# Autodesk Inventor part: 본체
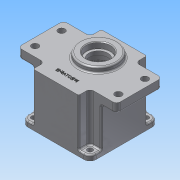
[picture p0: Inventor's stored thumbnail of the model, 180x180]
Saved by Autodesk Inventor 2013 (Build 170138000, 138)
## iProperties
Created: 2014-12
Part Number: 본체
Material: Aluminum 6061
Document SubType Name: Modeling
Designer: Administrator
Density: 2.71 g/cm^3
Mass: 705.358 g
Surface Area: 672.962 cm^2
Volume: 260.28 cm^3
Author: Administrator
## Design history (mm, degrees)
sketch "Sketch1"
  geometry: L1 (-37, 45)-(37, 45); L2 (45, 37)-(45, -37); L3 (37, -45)-(-37, -45); L4 (-45, -37)-(-45, 37); L5 (-45, 45)-(45, -45); L6 (45, 45)-(-45, -45); C1 r 3.5 at (-37, 37); C2 r 3.5 at (37, 37); C3 r 3.5 at (37, -37); C4 r 3.5 at (-37, -37); A1 r 8 centre (-37, 37) between (-37, 45) and (-45, 37); A2 r 8 centre (37, 37) between (45, 37) and (37, 45); A3 r 8 centre (37, -37) between (37, -45) and (45, -37); A4 r 8 centre (-37, -37) between (-45, -37) and (-37, -45); 1 further point
  constraints: 12 end point, 8 centre point, 8 point on circle, 8 point on line, 8 tangent, 4 coincident, 3 equal radius, 2 midpoint, 2 parallel, 1 horizontal, 1 perpendicular
  dimensions: "d0" = 90 distance of L5.end L6.end; "d1" = 90 distance of L6.start L5.end; "d2" = 8 radius of A1; "d3" = 7 diameter of C1; "d4" = 7 diameter of C2; "d5" = 7 diameter of C3; "d6" = 7 diameter of C4
extrude "Extrusion1" new body sketch "Sketch1" distance "d7" = 7; taper "d8" = 0 deg
sketch "Sketch2"
  geometry: L1 (-30, 45)-(30, 45); L2 (30, 45)-(30, -45); L3 (30, -45)-(-30, -45); L4 (-30, -45)-(-30, 45); L5 (-30, 45)-(30, -45); L6 (30, 45)-(-30, -45); L7 (-45, 30)-(45, 30); L8 (45, 30)-(45, -30); L9 (45, -30)-(-45, -30); L10 (-45, -30)-(-45, 30); L11 (-45, 30)-(45, -30); L12 (45, 30)-(-45, -30); 1 further point
  constraints: 24 end point, 4 midpoint, 4 parallel, 2 horizontal, 2 perpendicular
  dimensions: "d9" = 60 distance of L2.end L3.end; "d10" = 90 distance of L1.end L2.end; "d11" = 90 distance of L8.end L9.end; "d12" = 60 distance of L7.end L8.end
extrude "Extrusion2" join sketch "Sketch2" distance "d13" = 51; taper "d14" = 0 deg
sketch "Sketch3"
  geometry: L1 (-30, -30)-(-30, -45) reference; L2 (-30, -45)-(30, -45) reference; L3 (30, -45)-(30, -30) reference; L4 (30, -30)-(45, -30) reference; L5 (45, -30)-(45, 30) reference; L6 (45, 30)-(30, 30) reference; L7 (30, 30)-(30, 45) reference; L8 (30, 45)-(-30, 45) reference; L9 (-30, 45)-(-30, 30) reference; L10 (-30, 30)-(-45, 30) reference; L11 (-45, 30)-(-45, -30) reference; L12 (-45, -30)-(-30, -30) reference; L13 (-60, 30)-(60, 30); L14 (65, 25)-(65, -25); L15 (60, -30)-(-60, -30); L16 (-65, -25)-(-65, 25); L17 (-65, 30)-(65, -30); L18 (65, 30)-(-65, -30); A1 r 5 centre (-60, 25) between (-60, 30) and (-65, 25); A2 r 5 centre (60, 25) between (65, 25) and (60, 30); A3 r 5 centre (60, -25) between (60, -30) and (65, -25); A4 r 5 centre (-60, -25) between (-65, -25) and (-60, -30); 5 further points
  constraints: 12 end point, 8 point on circle, 8 point on line, 8 tangent, 4 centre point, 3 equal radius, 2 horizontal alignment, 2 midpoint, 2 parallel, 2 vertical alignment, 1 horizontal, 1 perpendicular
  dimensions: "d15" = 130 distance of L17.end L18.end; "d16" = 60 distance of L18.start L17.end; "d19" = 5 radius of A1; "d20" = 10 distance from line of L16 point (-55, 17.5); "d21" = 12.5 distance from line of L13 point (-55, 17.5); "d22" = 110 distance of point (55, 17.5) point (-55, 17.5); "d23" = 35 distance of point (-55, 17.5) point (-55, -17.5)
extrude "Extrusion3" join sketch "Sketch3" distance "d17" = 12; taper "d18" = 0 deg
hole "Hole1" sketch "Sketch3" diameter "d24" = 9; stored, may be unused: countersink angle "d28" = 90 deg, drill point angle "d30" = 118 deg; dims "d25" = 6, "d26" = 4, "d27" = 2, "d29" = 8
sketch "Sketch4"
  geometry: C1 r 25 at (0, 11); 1 further point
  constraints: 1 centre point, 1 vertical alignment
  dimensions: "d31" = 50 diameter of C1; "d32" = 11 distance of point (0, 0) C1.centre
extrude "Extrusion4" join sketch "Sketch4" distance "d33" = 7; taper "d34" = 0 deg
sketch "Sketch5"
  geometry: C1 r 40 at (0, 0); 1 further point
  constraints: 1 centre point, 1 coincident
  dimensions: "d35" = 80 diameter of C1
extrude "Extrusion5" cut sketch "Sketch5" distance "d36" = 9; taper "d37" = 0 deg
sketch "Sketch6"
  geometry: C1 r 40 at (0, 0) reference; C2 r 39 at (0, 0)
  constraints: 1 centre point, 1 coincident
  dimensions: "d38" = 78 diameter of C2
extrude "Extrusion6" cut sketch "Sketch6" distance "d39" = 52; taper "d40" = 0 deg
sketch "Sketch7"
  geometry: L1 (0, 0)-(0, 39); C1 r 40 at (0, 0) reference; A1 r 39 centre (0, 0) between (0, 39) and (32.777, 21.134) reference; A2 r 4 centre (24.749, 24.749) between (21.809, 27.462) and (27.462, 21.809); A3 r 3.5 centre (19.238, 29.836) between (21.809, 27.462) and (21.134, 32.777); A4 r 3.5 centre (29.836, 19.238) between (32.777, 21.134) and (27.462, 21.809); 1 further point
  constraints: 9 point on circle, 4 tangent, 3 centre point, 2 end point, 1 coincident, 1 vertical
  dimensions: "d41" = 8 diameter of A2; "d42" = 35 distance of A1.centre A2.centre; "d43" = 45 deg dimension on A1.centre A2.centre L1.end; "d44" = 7 diameter of A3; "d45" = 7 diameter of A4
extrude "Extrusion7" join sketch "Sketch7" stored distance "d46" = 52; taper "d47" = 0 deg
hole "Hole2" sketch "Sketch7" diameter "d48" = 3.459; stored, may be unused: countersink angle "d52" = 90 deg, drill point angle "d54" = 118 deg; dims "d49" = 12, "d50" = 4, "d51" = 2, "d53" = 15
pattern_circular "Circular Pattern1" dims angle "d56" = 360 deg
sketch "Sketch8"
  geometry: A1 r 39 centre (0, 0) between (-32.777, 21.134) and (-32.777, -21.134) reference; A2 r 20.5 centre (0, 11) between (11.115, -6.225) and (-11.115, -6.225); A3 r 14 centre (0, -20) between (-10.493, -10.732) and (10.493, -10.732); A4 r 3 centre (-12.742, -8.746) between (-10.493, -10.732) and (-11.115, -6.225); A5 r 3 centre (12.742, -8.746) between (11.115, -6.225) and (10.493, -10.732)
  constraints: 8 point on circle, 4 centre point, 4 tangent, 2 vertical alignment, 1 equal radius
  dimensions: "d58" = 41 diameter of A2; "d59" = 28 diameter of A3; "d60" = 11 distance of A1.centre A2.centre; "d61" = 20 distance of A3.centre A1.centre; "d62" = 3 radius of A4
extrude "Extrusion8" join sketch "Sketch8" distance "d63" = 7; taper "d64" = 0 deg
sketch "Sketch9"
  geometry: C1 r 25 at (0, 0) reference; 2 further points
  constraints: 1 coincident
hole "Hole3" sketch "Sketch9" at (0, 0) diameter "d65" = 25; stored, may be unused: countersink angle "d69" = 90 deg, drill point angle "d71" = 118 deg; dims "d66" = 12, "d67" = 32, "d68" = 8, "d70" = 15
sketch "Sketch10"
  geometry: C1 r 12.5 at (0, 11) reference; C2 r 17.5 at (0, 11); A1 r 14 centre (0, -20) between (-10.493, -10.732) and (10.493, -10.732) reference; A2 r 20.5 centre (0, 11) between (11.115, -6.225) and (-11.115, -6.225) reference; 2 further points
  constraints: 2 coincident, 1 centre point
  dimensions: "d72" = 35 diameter of C2
extrude "Extrusion9" cut sketch "Sketch10" distance "d73" = 10; taper "d74" = 0 deg
hole "Hole4" sketch "Sketch10" diameter "d75" = 19; stored, may be unused: countersink angle "d79" = 90 deg, drill point angle "d81" = 0 deg; dims "d76" = 12, "d77" = 22, "d78" = 7, "d80" = 8
chamfer "Chamfer1" distance "d82" = 1; stored, may be unused: second distance "d83" = 2, angle "d84" = 45 deg
fillet "Fillet1" dims "d85" = 5, "d86" = 0.3, "d87" = 2
sketch "Sketch11"
  geometry: L1 (-28, -45)-(28, -45) reference; C1 r 27 at (0, 11) reference; 2 further points
  constraints: 1 vertical alignment, 1 other
  dimensions: "d88" = 15 distance from line of L1 point (0, -30)
emboss "Emboss1" sketch "Sketch11" dims "d0" = 90, "d1" = 90, "d2" = 8, "d3" = 7, "d4" = 7, "d5" = 7, "d6" = 7, "d89" = 0.5, "d90" = 0
body "Solid1"
